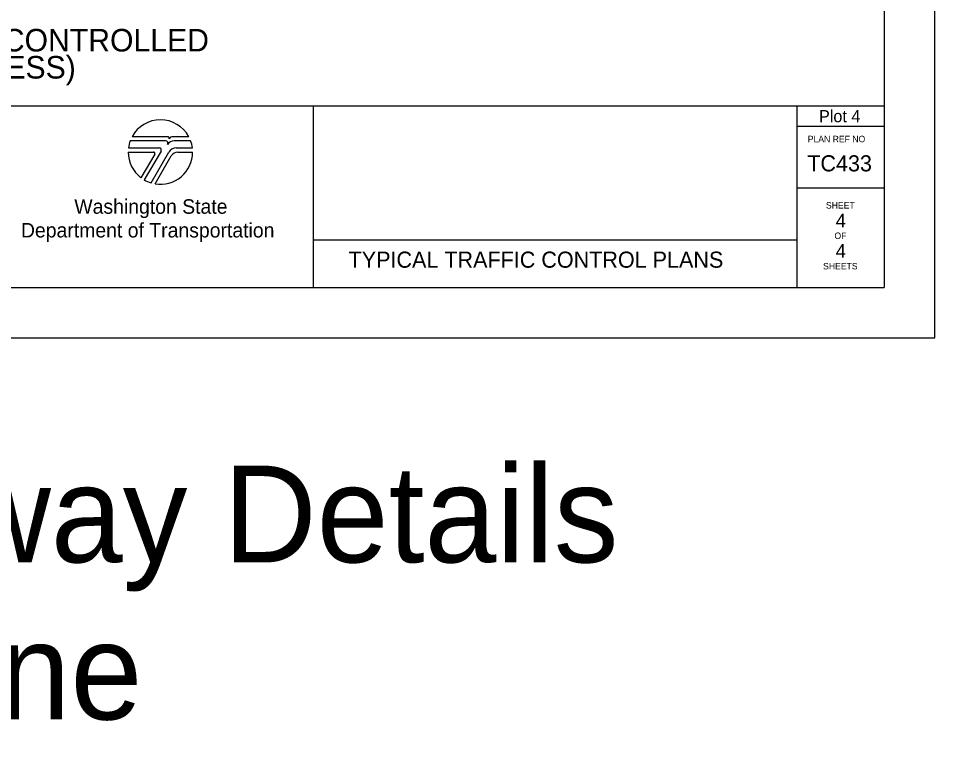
# Model space of a CAD drawing. Extents: x 99999.1 to 100095.7, y 99995 to 100010.7.
# Drawn here: x 100070.38 to 100076.06, y 99997.14 to 100001.67 of the extents above; entities that cross this region are included whole.
import ezdxf

# ---------------------------------------------------------------- set-up
doc = ezdxf.new("R2010")
doc.units = 0
for name, color, linetype in [('SH_DE_DetailHeading1Text', 7, 'Continuous'), ('SH_GI_PlotLimits', 7, 'Continuous'), ('SH_GI_SheetBorder', 7, 'Continuous'), ('SH_GI_SheetLocationText', 7, 'Continuous'), ('SH_GI_SheetTextInCells', 7, 'Continuous'), ('SH_GI_TitleBlockText', 7, 'Continuous'), ('SH_GI_WSDOTLogo', 7, 'Continuous')]:
    doc.layers.add(name, color=color, linetype=linetype)

msp = doc.modelspace()

# ---------------------------------------------------------------- linework, layer by layer
at = {"layer": 'SH_GI_PlotLimits'}
msp.add_lwpolyline([(100059.0625, 99999.6875), (100076.0625, 99999.6875), (100076.0625, 100010.6875), (100059.0625, 100010.6875)], close=True, dxfattribs=at)
at = {"layer": 'SH_GI_SheetBorder'}
for p, q in [((100075.75, 100010.375), (100075.75, 100000)), ((100060, 100001.1259), (100075.75, 100001.1259)), ((100072.2055, 100001.1259), (100072.2055, 100000)), ((100075.2079, 100001.1259), (100075.2079, 100000)), ((100075.2079, 100001.0008), (100075.75, 100001.0008)), ((100075.2079, 100000.6176), (100075.75, 100000.6176)), ((100072.2055, 100000.2955), (100075.2079, 100000.2955)), ((100060, 100000), (100075.75, 100000))]:
    msp.add_line(p, q, dxfattribs=at)
at = {"layer": 'SH_GI_WSDOTLogo'}
for p, q in [((100071.2894, 100000.9094), (100071.0697, 100000.9094)), ((100071.303, 100000.9354), (100071.0815, 100000.9354)), ((100071.433, 100000.9354), (100071.3351, 100000.9354)), ((100071.343, 100000.9094), (100071.3429, 100000.9094)), ((100071.4448, 100000.9094), (100071.343, 100000.9094)), ((100071.0572, 100000.84), (100071.2148, 100000.84)), ((100071.059, 100000.8661), (100071.2496, 100000.8661)), ((100071.261, 100000.8464), (100071.1567, 100000.6672)), ((100071.1989, 100000.6487), (100071.3089, 100000.839)), ((100071.3558, 100000.8661), (100071.4555, 100000.8661)), ((100071.3655, 100000.8394), (100071.4572, 100000.8394)), ((100071.222, 100000.8277), (100071.1364, 100000.6807)), ((100071.2244, 100000.6428), (100071.3242, 100000.8156))]:
    msp.add_line(p, q, dxfattribs=at)
for centre, radius, start, end in [((100071.2572, 100000.84), 0.2, 28.4787, 151.532), ((100071.2572, 100000.84), 0.2, 159.696, 172.5057), ((100071.2894, 100000.8946), 0.0148, 327.8418, 89.9985), ((100071.3429, 100000.861), 0.0484, 89.9953, 147.8238), ((100071.303, 100000.9263), 0.00903, 329.8742, 90.0033), ((100071.3352, 100000.9066), 0.0287, 90.0072, 148.1676), ((100071.2572, 100000.84), 0.2, 7.4943, 20.2941), ((100071.2572, 100000.84), 0.2, 179.9986, 232.8433), ((100071.2149, 100000.8318), 0.0082, 329.7436, 90), ((100071.2572, 100000.84), 0.2, 260.5455, 359.8086), ((100071.2497, 100000.853), 0.0131, 329.7683, 90), ((100071.3558, 100000.8119), 0.0542, 90, 149.9974), ((100071.3654, 100000.7918), 0.0476, 90, 150.0543), ((100071.2572, 100000.84), 0.2, 239.7929, 253.0448)]:
    msp.add_arc(centre, radius, start, end, dxfattribs=at)

# ---------------------------------------------------------------- texts
at = {"layer": 'SH_DE_DetailHeading1Text'}
for s, p in [('PILOT CAR OPERATION FOR ALTERNATING 1-LANE, 2-WAY TRAFFIC: AFAD-CONTROLLED', (100063.4137, 100001.4639)), ('SEPARATED BICYCLE LANE STRATEGY (HIGHWAYS, 40 MPH OR LESS)', (100064.3029, 100001.2959))]:
    msp.add_text(s, height=0.14, rotation=360, dxfattribs=at).set_placement(p)
at = {"layer": 'SH_GI_SheetBorder'}
msp.add_text('PLAN REF NO', height=0.040032, dxfattribs=at).set_placement((100075.2747, 100000.9008))
at = {"layer": 'SH_GI_SheetLocationText'}
for s, height, p in [('Plot 4', 0.075, (100075.3447, 100001.025)), ('Access & Intersecting Roadway Details', 0.6, (100060.1422, 99998.2946)), ('Separated Bike Lane', 0.6, (100063.6511, 99997.3196))]:
    msp.add_text(s, height=height, dxfattribs=at).set_placement(p)
at = {"layer": 'SH_GI_SheetTextInCells'}
for s, height, p in [('Washington State', 0.090072, (100070.7229, 100000.4571)), ('SHEET', 0.04003, (100075.3877, 100000.4896)), ('Department of Transportation', 0.090072, (100070.3916, 100000.3101)), ('OF', 0.04003, (100075.4406, 100000.3008)), ('SHEETS', 0.04003, (100075.3698, 100000.112))]:
    msp.add_text(s, height=height, dxfattribs=at).set_placement(p)
at = {"layer": 'SH_GI_TitleBlockText'}
for s, height, p in [('TC433', 0.1, (100075.2718, 100000.72)), ('4', 0.085, (100075.4485, 100000.3723)), ('4', 0.085, (100075.4485, 100000.1843)), ('TYPICAL TRAFFIC CONTROL PLANS', 0.1, (100072.4251, 100000.1224))]:
    msp.add_text(s, height=height, dxfattribs=at).set_placement(p)

doc.saveas('drawing.dxf')
